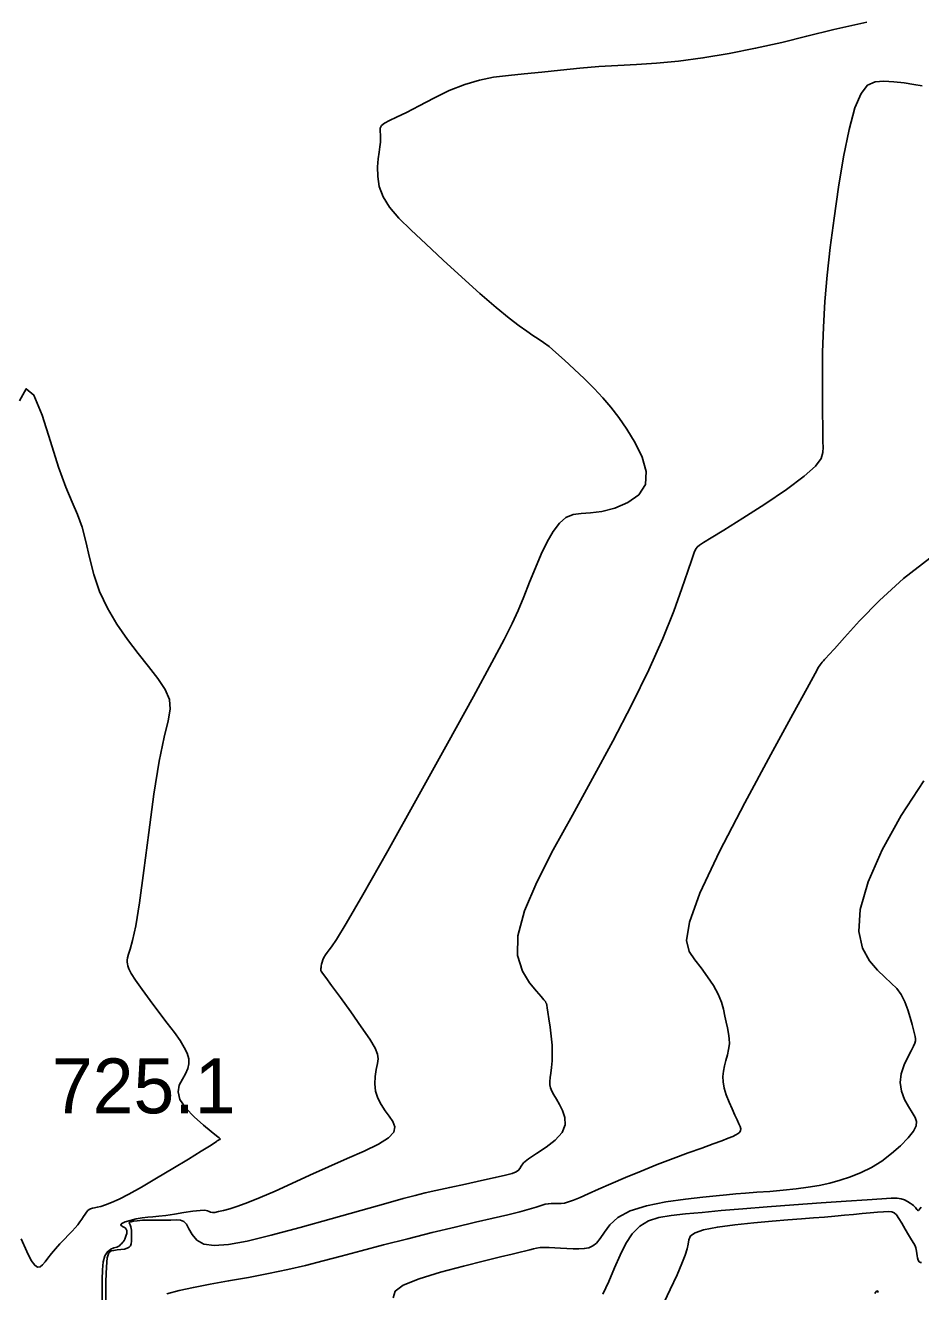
# Model space of a CAD drawing. Extents: x 2566142 to 2571431, y 418755 to 421584.
# Drawn here: x 2569091.5 to 2569336.4, y 420498.8 to 420845.1 of the extents above; entities that cross this region are included whole.
import ezdxf

# ---------------------------------------------------------------- set-up
doc = ezdxf.new("R2010")
doc.units = 0
for name, color, linetype in [('Contour_ADS_Major', 7, 'Continuous'), ('Contour_ADS_Minor', 7, 'Continuous'), ('Contour_ADS_Spot_Elevation', 7, 'Continuous')]:
    doc.layers.add(name, color=color, linetype=linetype)

msp = doc.modelspace()

# ---------------------------------------------------------------- linework, layer by layer
at = {"layer": 'Contour_ADS_Major'}
for points in [[(2569336.8, 420828.55), (2569334.58, 420828.94), (2569331.91, 420829.36), (2569329.07, 420829.71), (2569326.35, 420829.87), (2569323.98, 420829.68), (2569321.92, 420828.73), (2569320.11, 420826.52), (2569318.43, 420822.58), (2569316.83, 420816.63), (2569315.32, 420809.15), (2569313.94, 420800.85), (2569312.72, 420792.4), (2569311.7, 420784.39), (2569310.87, 420776.82), (2569310.25, 420769.58), (2569309.84, 420762.58), (2569309.61, 420755.78), (2569309.54, 420749.38), (2569309.55, 420743.7), (2569309.6, 420739.02), (2569309.64, 420735.54), (2569309.66, 420733.04), (2569309.69, 420731.2), (2569309.72, 420729.73), (2569309.7, 420728.31), (2569309.17, 420726.69), (2569307.64, 420724.61)], [(2569307.64, 420724.61), (2569304.57, 420721.82), (2569299.71, 420718.21), (2569293.78, 420714.19), (2569287.76, 420710.31), (2569282.62, 420707.09), (2569279.11, 420704.95), (2569277.02, 420703.7), (2569275.92, 420703.01), (2569275.36, 420702.55), (2569274.96, 420701.99), (2569274.51, 420700.94), (2569273.82, 420699.03), (2569272.75, 420695.84), (2569271.13, 420691.1), (2569268.87, 420684.9), (2569265.88, 420677.41), (2569262.09, 420668.84), (2569257.46, 420659.39), (2569252.24, 420649.39), (2569246.7, 420639.19), (2569241.16, 420629.16), (2569235.93, 420619.63), (2569231.41, 420610.81), (2569228.02, 420602.93), (2569226.2, 420596.18), (2569226.19, 420590.72), (2569227.49, 420586.47), (2569229.42, 420583.28), (2569231.32, 420581.01), (2569232.63, 420579.52), (2569233.39, 420578.63), (2569233.78, 420578.14), (2569233.94, 420577.85), (2569234.04, 420577.59), (2569234.14, 420577.18), (2569234.26, 420576.45), (2569234.46, 420575.24), (2569234.75, 420573.44), (2569235.08, 420571.2), (2569235.38, 420568.74), (2569235.59, 420566.28), (2569235.66, 420564), (2569235.6, 420561.94), (2569235.46, 420560.14), (2569235.29, 420558.62), (2569235.12, 420557.36), (2569235.01, 420556.32), (2569235.01, 420555.4), (2569235.18, 420554.53), (2569235.56, 420553.62), (2569236.12, 420552.62), (2569236.83, 420551.44), (2569237.65, 420550.04), (2569238.5, 420548.35), (2569239.11, 420546.46), (2569239.17, 420544.42), (2569238.34, 420542.34), (2569236.47, 420540.3), (2569233.95, 420538.36), (2569231.33, 420536.62), (2569229.14, 420535.16), (2569227.8, 420534.02), (2569227.12, 420533.16), (2569226.77, 420532.52), (2569226.44, 420532.03), (2569225.81, 420531.6), (2569224.67, 420531.18), (2569222.82, 420530.69), (2569220.05, 420530.04), (2569216.28, 420529.21), (2569211.95, 420528.27), (2569207.61, 420527.33), (2569203.81, 420526.5), (2569200.88, 420525.84), (2569198.19, 420525.17), (2569194.88, 420524.28), (2569190.11, 420522.93), (2569183.33, 420521), (2569175.19, 420518.7), (2569166.68, 420516.34), (2569158.77, 420514.25), (2569152.24, 420512.68), (2569147.11, 420511.73), (2569143.21, 420511.43), (2569140.39, 420511.84), (2569138.44, 420512.93), (2569137.16, 420514.42), (2569136.29, 420515.98), (2569135.59, 420517.28), (2569134.86, 420518.05), (2569133.97, 420518.39), (2569132.83, 420518.45), (2569131.35, 420518.41), (2569129.5, 420518.38), (2569127.44, 420518.38), (2569125.39, 420518.38), (2569123.57, 420518.34), (2569122.14, 420518.24), (2569121.1, 420518.11), (2569120.43, 420517.95)], [(2569120.43, 420517.95), (2569120.06, 420517.8), (2569119.96, 420517.66), (2569120.04, 420517.45), (2569120.22, 420517.11), (2569120.4, 420516.54), (2569120.53, 420515.69), (2569120.59, 420514.67), (2569120.59, 420513.62), (2569120.55, 420512.67), (2569120.46, 420511.92), (2569120.28, 420511.37), (2569119.95, 420510.97), (2569119.4, 420510.69), (2569118.61, 420510.49), (2569117.65, 420510.34), (2569116.66, 420510.23), (2569115.73, 420510.13), (2569114.96, 420509.98), (2569114.37, 420509.44), (2569113.95, 420508.12), (2569113.69, 420505.63), (2569113.59, 420501.71), (2569113.59, 420496.58)], [(2569324.84, 420498.59), (2569324.62, 420499.05), (2569324.29, 420498.9), (2569323.88, 420498.31)]]:
    msp.add_lwpolyline(points, dxfattribs=at)
at = {"layer": 'Contour_ADS_Minor'}
for points in [[(2569321.72, 420845.98), (2569312.69, 420844.01), (2569305.27, 420842.17), (2569298.42, 420840.45), (2569291.29, 420838.85), (2569284, 420837.42), (2569276.85, 420836.22), (2569270.16, 420835.32), (2569264.17, 420834.76), (2569258.71, 420834.42), (2569253.55, 420834.18), (2569248.43, 420833.89), (2569243.17, 420833.45), (2569237.89, 420832.91), (2569232.77, 420832.34), (2569227.98, 420831.83), (2569223.65, 420831.4), (2569219.62, 420830.91), (2569215.71, 420830.17), (2569211.7, 420828.99), (2569207.47, 420827.27), (2569203.23, 420825.21), (2569199.24, 420823.12), (2569195.79, 420821.3), (2569193.09, 420819.98), (2569191.12, 420819.06), (2569189.78, 420818.37), (2569188.98, 420817.72), (2569188.62, 420816.98), (2569188.55, 420816.14), (2569188.64, 420815.21), (2569188.72, 420814.21), (2569188.68, 420813.14), (2569188.53, 420811.92), (2569188.32, 420810.45), (2569188.08, 420808.63), (2569187.89, 420806.39), (2569187.92, 420803.83), (2569188.35, 420801.07), (2569189.37, 420798.24), (2569191.15, 420795.41), (2569193.7, 420792.44), (2569197.02, 420789.15), (2569201.1, 420785.35), (2569205.86, 420780.95), (2569210.93, 420776.29), (2569215.89, 420771.81), (2569220.3, 420767.94), (2569223.83, 420765.02), (2569226.56, 420762.93), (2569228.68, 420761.45), (2569230.37, 420760.34), (2569231.83, 420759.4), (2569233.23, 420758.43), (2569234.78, 420757.26)], [(2569234.78, 420757.26), (2569236.66, 420755.68), (2569239.01, 420753.6), (2569241.67, 420751.12), (2569244.44, 420748.46), (2569247.11, 420745.78), (2569249.51, 420743.23), (2569251.72, 420740.67), (2569253.86, 420737.9), (2569256.04, 420734.71), (2569258.29, 420731), (2569260.22, 420727.01), (2569261.33, 420723.09), (2569261.15, 420719.58), (2569259.35, 420716.74), (2569256.36, 420714.6), (2569252.78, 420713.11), (2569249.22, 420712.22), (2569246.15, 420711.84), (2569243.57, 420711.67), (2569241.36, 420711.36), (2569239.41, 420710.56), (2569237.6, 420709.01), (2569235.89, 420706.73), (2569234.24, 420703.85), (2569232.63, 420700.48), (2569231.03, 420696.74), (2569229.44, 420692.81), (2569227.87, 420688.88), (2569226.31, 420685.12), (2569224.68, 420681.52), (2569222.49, 420677.15), (2569219.15, 420670.9), (2569214.07, 420661.62), (2569206.96, 420648.74), (2569198.75, 420633.93), (2569190.64, 420619.4), (2569183.85, 420607.36), (2569179.29, 420599.48), (2569176.64, 420595.13), (2569175.28, 420593.12), (2569174.59, 420592.27), (2569174.06, 420591.6), (2569173.6, 420590.91), (2569173.21, 420590.23), (2569172.91, 420589.57), (2569172.7, 420588.94), (2569172.56, 420588.36), (2569172.47, 420587.87), (2569172.41, 420587.47), (2569172.36, 420587.18), (2569172.33, 420586.98), (2569172.32, 420586.83), (2569172.34, 420586.7), (2569172.45, 420586.49), (2569172.83, 420585.95), (2569173.7, 420584.75), (2569175.29, 420582.58), (2569177.7, 420579.28), (2569180.56, 420575.31), (2569183.4, 420571.29), (2569185.73, 420567.84), (2569187.19, 420565.4), (2569187.87, 420563.74), (2569188.01, 420562.47), (2569187.83, 420561.19), (2569187.52, 420559.59), (2569187.25, 420557.7), (2569187.15, 420555.68), (2569187.35, 420553.66), (2569187.95, 420551.75), (2569188.86, 420549.98), (2569189.93, 420548.32), (2569191.04, 420546.78), (2569192.02, 420545.34), (2569192.55, 420543.94), (2569192.28, 420542.49), (2569190.87, 420540.92), (2569188.09, 420539.18), (2569184.18, 420537.26), (2569179.52, 420535.2), (2569174.46, 420532.99), (2569169.36, 420530.7), (2569164.42, 420528.43), (2569159.83, 420526.34), (2569155.77, 420524.56), (2569152.38, 420523.2), (2569149.62, 420522.21), (2569147.42, 420521.52), (2569145.69, 420521.04), (2569144.37, 420520.72), (2569143.4, 420520.52), (2569142.69, 420520.46), (2569142.21, 420520.53), (2569141.84, 420520.71), (2569141.4, 420520.92), (2569140.64, 420521.07), (2569139.33, 420521.06), (2569137.33, 420520.84), (2569134.87, 420520.47), (2569132.29, 420520.05)], [(2569089.91, 420742.47), (2569091.77, 420745.73), (2569093.88, 420744), (2569096.14, 420738.56), (2569098.43, 420731.35), (2569100.61, 420724.26), (2569102.58, 420718.8), (2569104.3, 420714.72), (2569105.79, 420711.32), (2569107.03, 420707.92), (2569108.06, 420704), (2569109.07, 420699.61), (2569110.25, 420694.96), (2569111.85, 420690.26), (2569114, 420685.7), (2569116.6, 420681.34), (2569119.46, 420677.21), (2569122.41, 420673.35), (2569125.26, 420669.8), (2569127.78, 420666.52), (2569129.75, 420663.52)], [(2569338.93, 420699.45), (2569331.69, 420693.85), (2569325.2, 420687.88), (2569319.73, 420682.26), (2569315.56, 420677.68), (2569312.83, 420674.65), (2569311.28, 420672.94), (2569310.51, 420672.1), (2569310.13, 420671.69), (2569309.82, 420671.36), (2569309.51, 420671.01), (2569309.2, 420670.64), (2569308.91, 420670.24), (2569308.52, 420669.6), (2569307.55, 420667.85), (2569305.39, 420663.91), (2569301.44, 420656.73), (2569295.42, 420645.75), (2569288.32, 420632.53), (2569281.44, 420619.17), (2569276.06, 420607.76), (2569273.16, 420599.84), (2569272.41, 420594.89), (2569273.12, 420591.84), (2569274.65, 420589.61), (2569276.39, 420587.35), (2569278.13, 420584.96), (2569279.73, 420582.54), (2569281.02, 420580.21), (2569281.93, 420578.04), (2569282.51, 420576.04), (2569282.9, 420574.2), (2569283.22, 420572.51), (2569283.55, 420570.95), (2569283.85, 420569.47), (2569284.06, 420568.03), (2569284.09, 420566.58), (2569283.9, 420565.09), (2569283.56, 420563.57), (2569283.16, 420562.05), (2569282.77, 420560.57), (2569282.48, 420559.14), (2569282.34, 420557.71), (2569282.4, 420556.19), (2569282.7, 420554.51), (2569283.26, 420552.64), (2569284.01, 420550.68), (2569284.82, 420548.79), (2569285.6, 420547.12), (2569286.24, 420545.79), (2569286.73, 420544.76), (2569287.06, 420543.97), (2569287.21, 420543.36), (2569287.17, 420542.87), (2569286.95, 420542.46), (2569286.52, 420542.09), (2569285.88, 420541.71), (2569285.01, 420541.29), (2569283.78, 420540.77), (2569282.05, 420540.1), (2569279.68, 420539.22), (2569276.57, 420538.1), (2569272.86, 420536.77), (2569268.73, 420535.24), (2569264.36, 420533.58), (2569259.94, 420531.81), (2569255.66, 420530.03), (2569251.7, 420528.34), (2569248.26, 420526.83), (2569245.46, 420525.58), (2569243.25, 420524.59), (2569241.51, 420523.85), (2569240.14, 420523.35), (2569239.03, 420523.05), (2569238.12, 420522.93), (2569237.35, 420522.91), (2569236.67, 420522.94), (2569236.03, 420522.97), (2569235.36, 420522.97), (2569234.61, 420522.89), (2569233.73, 420522.71), (2569232.64, 420522.39), (2569231.22, 420521.93), (2569229.31, 420521.35)], [(2569129.75, 420663.52), (2569130.92, 420660.77), (2569131.14, 420658.12), (2569130.58, 420654.93), (2569129.49, 420650.44), (2569128.13, 420643.87), (2569126.71, 420634.84), (2569125.31, 420624.4), (2569123.98, 420614.02), (2569122.77, 420605.13), (2569121.72, 420598.83), (2569120.85, 420594.82), (2569120.17, 420592.46), (2569119.71, 420591.09), (2569119.46, 420590.16), (2569119.37, 420589.48), (2569119.4, 420588.94), (2569119.47, 420588.45), (2569119.58, 420587.89), (2569119.86, 420587.09), (2569120.49, 420585.86), (2569121.65, 420584.03), (2569123.45, 420581.48), (2569125.68, 420578.46), (2569128.08, 420575.28), (2569130.36, 420572.27), (2569132.29, 420569.68), (2569133.84, 420567.5), (2569135.01, 420565.63), (2569135.8, 420564.01), (2569136.23, 420562.54), (2569136.29, 420561.17), (2569136, 420559.82), (2569135.37, 420558.44), (2569134.48, 420556.96), (2569133.65, 420555.32), (2569133.29, 420553.48), (2569133.79, 420551.38), (2569135.39, 420549.02), (2569137.72, 420546.61), (2569140.22, 420544.39), (2569142.39, 420542.62), (2569143.79, 420541.47), (2569144.52, 420540.86), (2569144.8, 420540.6), (2569144.83, 420540.52), (2569144.8, 420540.48), (2569144.75, 420540.44), (2569144.67, 420540.41), (2569144.58, 420540.37), (2569144.48, 420540.32), (2569144.35, 420540.25), (2569144.21, 420540.17), (2569144.04, 420540.05), (2569143.78, 420539.87), (2569143.17, 420539.47), (2569141.88, 420538.64), (2569139.59, 420537.21), (2569136.13, 420535.08), (2569131.9, 420532.5), (2569127.44, 420529.82), (2569123.28, 420527.41), (2569119.87, 420525.52), (2569117.18, 420524.14), (2569115.08, 420523.19), (2569113.46, 420522.55), (2569112.19, 420522.15), (2569111.21, 420521.92), (2569110.45, 420521.77), (2569109.86, 420521.65), (2569109.38, 420521.5), (2569108.97, 420521.28), (2569108.6, 420520.98), (2569108.24, 420520.56), (2569107.86, 420520.03), (2569107.44, 420519.39), (2569106.98, 420518.68), (2569106.46, 420517.93), (2569105.86, 420517.14), (2569105.17, 420516.31), (2569104.35, 420515.39), (2569103.36, 420514.34), (2569102.22, 420513.15), (2569100.98, 420511.87), (2569099.76, 420510.55), (2569098.64, 420509.25), (2569097.71, 420508.03), (2569096.92, 420506.98), (2569096.23, 420506.16), (2569095.57, 420505.65), (2569094.88, 420505.55), (2569094.09, 420506.05), (2569093.13, 420507.39), (2569091.92, 420509.77), (2569090.43, 420513.28)], [(2569337.31, 420638.53), (2569331.08, 420629.02), (2569325.88, 420619.63), (2569322.02, 420610.89), (2569319.84, 420603.31), (2569319.48, 420597.31), (2569320.55, 420592.73), (2569322.46, 420589.29), (2569324.65, 420586.74), (2569326.65, 420584.79), (2569328.38, 420583.19), (2569329.86, 420581.7), (2569331.1, 420580.05), (2569332.11, 420578.07), (2569332.93, 420575.9), (2569333.59, 420573.77), (2569334.1, 420571.9), (2569334.49, 420570.45), (2569334.77, 420569.38), (2569334.95, 420568.59), (2569335.03, 420567.97), (2569335.01, 420567.43), (2569334.85, 420566.81), (2569334.47, 420565.95), (2569333.81, 420564.7), (2569332.88, 420562.96), (2569331.88, 420560.82), (2569331.09, 420558.44), (2569330.79, 420556), (2569331.14, 420553.62), (2569332, 420551.41), (2569333.08, 420549.44), (2569334.14, 420547.79), (2569334.94, 420546.47), (2569335.33, 420545.33), (2569335.2, 420544.15), (2569334.44, 420542.71), (2569332.99, 420540.87), (2569330.95, 420538.75), (2569328.49, 420536.57), (2569325.79, 420534.54), (2569322.99, 420532.81), (2569320.14, 420531.39), (2569317.26, 420530.23), (2569314.4, 420529.28), (2569311.56, 420528.51), (2569308.67, 420527.87), (2569305.64, 420527.36), (2569302.36, 420526.93), (2569298.81, 420526.57), (2569295.16, 420526.26), (2569291.65, 420526), (2569288.51, 420525.77), (2569285.86, 420525.56), (2569283.35, 420525.34), (2569280.5, 420525.06), (2569276.84, 420524.68), (2569272.1, 420524.14), (2569266.75, 420523.39), (2569261.47, 420522.34), (2569256.93, 420520.91), (2569253.62, 420519.09), (2569251.4, 420517.07), (2569249.9, 420515.08), (2569248.8, 420513.37), (2569247.8, 420512.13), (2569246.79, 420511.32), (2569245.68, 420510.85), (2569244.42, 420510.6), (2569242.95, 420510.51), (2569241.33, 420510.52), (2569239.63, 420510.59), (2569237.94, 420510.69), (2569236.33, 420510.79), (2569234.84, 420510.87), (2569233.5, 420510.89), (2569232.35, 420510.86), (2569231.39, 420510.74), (2569230.51, 420510.55), (2569229.55, 420510.29), (2569228.4, 420509.98), (2569226.86, 420509.61), (2569224.68, 420509.09), (2569221.53, 420508.35), (2569217.13, 420507.28), (2569211.37, 420505.83), (2569205.07, 420504.12), (2569199.24, 420502.31), (2569194.88, 420500.56), (2569192.7, 420498.92), (2569192.12, 420497.1)], [(2569336.56, 420521.96), (2569336.17, 420521.45), (2569335.93, 420521.13), (2569335.75, 420521), (2569335.57, 420521.07), (2569335.36, 420521.29), (2569335.16, 420521.57), (2569334.99, 420521.84), (2569334.84, 420522.04), (2569334.68, 420522.21), (2569334.45, 420522.4), (2569334.09, 420522.68), (2569333.55, 420523.06), (2569332.86, 420523.51), (2569332.03, 420523.93), (2569331.09, 420524.25), (2569330, 420524.41), (2569328.38, 420524.4), (2569325.78, 420524.25), (2569321.77, 420523.98), (2569316.08, 420523.59), (2569309.18, 420523.12), (2569301.75, 420522.6), (2569294.43, 420522.06), (2569287.78, 420521.52), (2569281.88, 420521.01), (2569276.67, 420520.52), (2569272.13, 420520.08), (2569268.2, 420519.64), (2569264.84, 420519.07), (2569261.98, 420518.17), (2569259.57, 420516.75), (2569257.55, 420514.67), (2569255.81, 420511.99), (2569254.23, 420508.85), (2569252.69, 420505.34), (2569251.11, 420501.64), (2569249.53, 420498.16)], [(2569132.29, 420520.05), (2569129.92, 420519.69), (2569128, 420519.47), (2569126.42, 420519.33), (2569124.99, 420519.2), (2569123.52, 420519.01), (2569121.88, 420518.7), (2569120.24, 420518.31), (2569118.84, 420517.89), (2569117.92, 420517.48), (2569117.64, 420517.13), (2569117.86, 420516.82), (2569118.33, 420516.54), (2569118.82, 420516.25), (2569119.14, 420515.94), (2569119.3, 420515.59), (2569119.32, 420515.2), (2569119.25, 420514.75), (2569119.12, 420514.25), (2569118.95, 420513.72), (2569118.76, 420513.22), (2569118.55, 420512.79), (2569118.33, 420512.47), (2569118.12, 420512.23), (2569117.93, 420512.04), (2569117.76, 420511.87), (2569117.6, 420511.68), (2569117.4, 420511.47), (2569117.07, 420511.25), (2569116.54, 420511.03), (2569115.77, 420510.8), (2569114.87, 420510.42), (2569113.98, 420509.76), (2569113.27, 420508.66), (2569112.83, 420507.02), (2569112.63, 420504.83), (2569112.57, 420502.12), (2569112.57, 420498.93), (2569112.54, 420495.33)], [(2569229.31, 420521.35), (2569226.78, 420520.66), (2569223.5, 420519.86), (2569219.45, 420518.93), (2569214.64, 420517.82), (2569209.06, 420516.51), (2569202.78, 420514.99), (2569196.13, 420513.32), (2569189.53, 420511.63), (2569183.36, 420510.01), (2569177.9, 420508.55), (2569172.96, 420507.22), (2569168.19, 420506.01), (2569163.29, 420504.87), (2569158.02, 420503.77), (2569152.54, 420502.73), (2569147.13, 420501.75), (2569142.04, 420500.85), (2569137.51, 420500.01), (2569133.57, 420499.17), (2569130.25, 420498.22)], [(2569336.64, 420506.83), (2569336.35, 420506.76), (2569336.05, 420507), (2569335.78, 420507.46), (2569335.57, 420508.04), (2569335.43, 420508.66), (2569335.36, 420509.28), (2569335.3, 420509.87), (2569335.23, 420510.39), (2569335.11, 420510.84), (2569334.89, 420511.33), (2569334.52, 420512), (2569333.95, 420512.98), (2569333.14, 420514.35), (2569332.2, 420515.94), (2569331.25, 420517.53), (2569330.41, 420518.87), (2569329.77, 420519.81), (2569329.19, 420520.36), (2569328.53, 420520.63), (2569327.6, 420520.71), (2569326.28, 420520.68), (2569324.59, 420520.56), (2569322.62, 420520.39), (2569320.43, 420520.18), (2569318.07, 420519.95), (2569315.56, 420519.71), (2569312.91, 420519.47), (2569310.1, 420519.23), (2569307.12, 420519), (2569303.84, 420518.76), (2569300.11, 420518.47), (2569295.76, 420518.11), (2569290.77, 420517.66), (2569285.6, 420517.12), (2569280.83, 420516.49), (2569277.06, 420515.76), (2569274.71, 420514.96), (2569273.5, 420514.05), (2569273.01, 420513.02), (2569272.81, 420511.85), (2569272.53, 420510.5), (2569272, 420508.78), (2569271.12, 420506.49), (2569269.79, 420503.41), (2569267.91, 420499.39), (2569265.51, 420494.39)]]:
    msp.add_lwpolyline(points, dxfattribs=at)

# ---------------------------------------------------------------- texts
at = {"layer": 'Contour_ADS_Spot_Elevation'}
msp.add_text('725.1', height=15, dxfattribs=at).set_placement((2569098.8, 420547.6))

doc.saveas('drawing.dxf')
